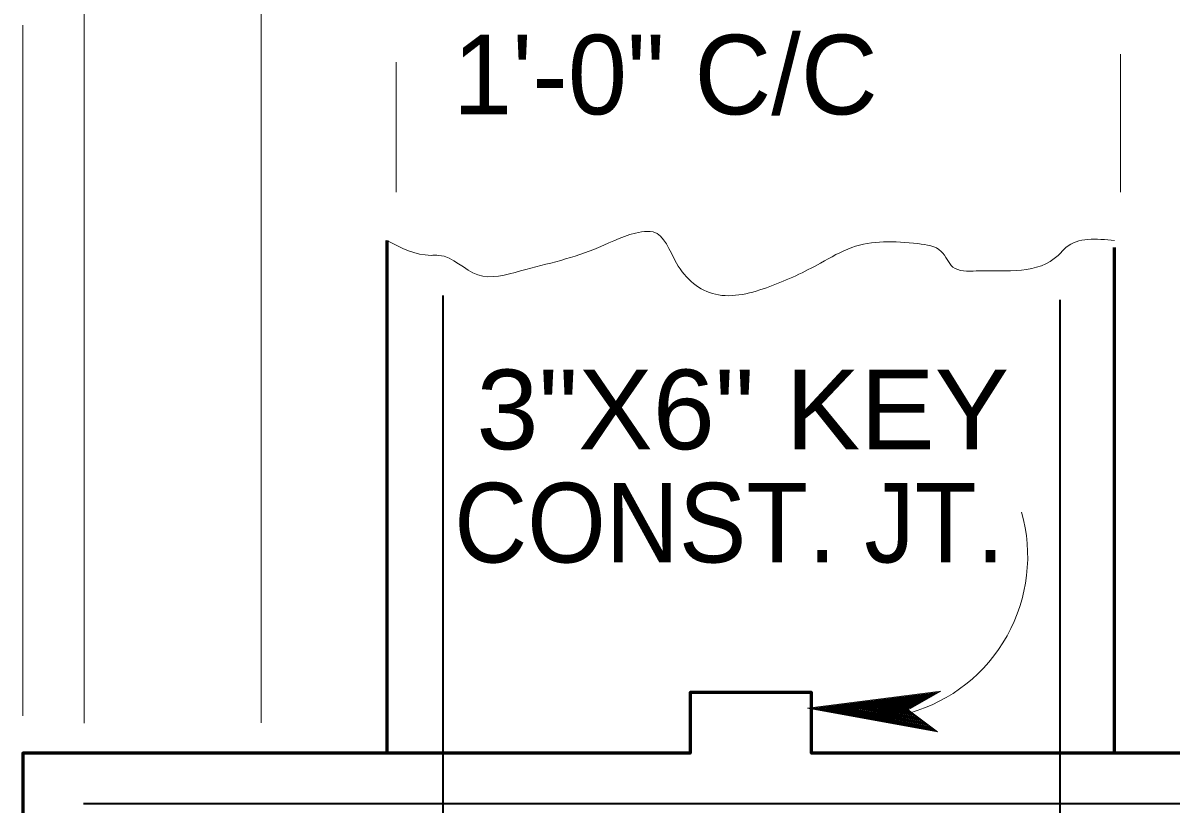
# Model space of a CAD drawing. Extents: x 144 to 252, y 360 to 425.
# Drawn here: x 190.824 to 195.557, y 413.625 to 416.844 of the extents above; entities that cross this region are included whole.
import ezdxf
from ezdxf.enums import TextEntityAlignment as Align

# ---------------------------------------------------------------- set-up
doc = ezdxf.new("R2010")
doc.units = 0
doc.header["$LTSCALE"] = 0.13
for name, color, linetype, lineweight in [('1', 7, 'Continuous', 40), ('14', 7, 'Continuous', 13), ('16', 7, 'Continuous', 13), ('3', 7, 'Continuous', 13), ('4', 7, 'Continuous', 35)]:
    doc.layers.add(name, color=color, linetype=linetype, lineweight=lineweight)

msp = doc.modelspace()

# ---------------------------------------------------------------- linework, layer by layer
at = {"layer": '1', "lineweight": 60}
for p, q in [((192.324, 415.9471), (192.324, 413.8347)), ((195.324, 413.8347), (195.324, 415.9182))]:
    msp.add_line(p, q, dxfattribs=at)
msp.add_lwpolyline([(190.824, 411.8347), (196.824, 411.8347), (196.824, 413.8347), (194.074, 413.8347), (194.074, 414.0847), (193.574, 414.0847), (193.574, 413.8347), (190.824, 413.8347)], close=True, dxfattribs=at)
at = {"layer": '1', "lineweight": 13}
msp.add_spline([(192.324, 415.9471), (192.5062, 415.8861), (192.5383, 415.8861), (192.6989, 415.8058), (192.8755, 415.8218), (193.1967, 415.9182), (193.3732, 415.9824), (193.4214, 415.9824), (193.5178, 415.854), (193.6783, 415.7255), (193.9031, 415.7577), (194.1118, 415.854), (194.2403, 415.9182), (194.5132, 415.9342), (194.6096, 415.9022), (194.6577, 415.8379), (194.7541, 415.8218), (195.0913, 415.8861), (195.1234, 415.9182), (195.324, 415.9471)], degree=3, dxfattribs=at)
at = {"layer": '14', "lineweight": 35}
for points in [[(192.5547, 415.7202), (192.5547, 412.2202), (191.5547, 412.2202)], [(195.0983, 415.7031), (195.0983, 412.2031), (196.0983, 412.2031)]]:
    msp.add_lwpolyline(points, dxfattribs=at)
at = {"layer": '14'}
msp.add_arc((194.2952, 414.6451), 0.6707, 285.8346, 15.8378, dxfattribs=at)
at = {"layer": '3'}
for p, q in [((191.0765, 413.9588), (191.0765, 417.2929)), ((191.8061, 413.9589), (191.8061, 417.2929)), ((190.824, 413.9885), (190.824, 416.8341)), ((190.824, 416.7245), (190.824, 416.7656)), ((192.3625, 416.1465), (192.3625, 416.6827)), ((195.3489, 416.1465), (195.3489, 416.7148)), ((190.824, 414.2097), (190.824, 416.1353)), ((190.824, 414.2097), (190.824, 415.5598)), ((194.6072, 414.0897), (194.0575, 414.0195)), ((194.6012, 414.0863), (194.0718, 414.0187)), ((194.5976, 414.0843), (194.0827, 414.0184)), ((194.5931, 414.0817), (194.0971, 414.0183)), ((194.5888, 414.0793), (194.1098, 414.0181)), ((194.5888, 414.0793), (194.1098, 414.0181)), ((194.5853, 414.0772), (194.1212, 414.0179)), ((194.5806, 414.0746), (194.1357, 414.0178)), ((194.4726, 414.0137), (194.6072, 414.0897)), ((194.5764, 414.0722), (194.1483, 414.0176)), ((194.5721, 414.0697), (194.1621, 414.0174)), ((194.5676, 414.0673), (194.1759, 414.0172)), ((194.5632, 414.0648), (194.1892, 414.017)), ((194.5588, 414.0623), (194.2031, 414.0168)), ((194.5547, 414.0601), (194.2157, 414.0166)), ((194.5509, 414.0578), (194.2272, 414.0165)), ((194.5459, 414.0551), (194.2428, 414.0163)), ((194.5414, 414.0525), (194.2566, 414.0161)), ((194.5342, 414.0484), (194.2746, 414.0154)), ((194.5374, 414.0503), (194.2762, 414.0169)), ((194.5298, 414.0459), (194.2885, 414.0152)), ((194.5255, 414.0435), (194.3017, 414.015)), ((194.5241, 414.0426), (194.3107, 414.0153)), ((194.52, 414.0405), (194.3227, 414.0152)), ((194.5156, 414.0379), (194.3366, 414.015)), ((194.5106, 414.0351), (194.3522, 414.0147)), ((194.5064, 414.0327), (194.3648, 414.0147)), ((194.5023, 414.0302), (194.3782, 414.0144)), ((194.4982, 414.0281), (194.39, 414.0143)), ((194.4936, 414.0254), (194.4046, 414.0141)), ((194.0575, 414.0195), (194.5938, 413.9229)), ((194.4727, 414.0137), (194.0575, 414.0195)), ((194.0718, 414.0187), (194.5906, 413.9253)), ((194.0827, 414.0184), (194.5874, 413.9277)), ((194.0971, 414.0183), (194.5832, 413.9307)), ((194.1098, 414.0181), (194.5795, 413.9335)), ((194.1212, 414.0179), (194.5762, 413.936)), ((194.1357, 414.0178), (194.572, 413.9392)), ((194.1483, 414.0176), (194.5683, 413.942)), ((194.1621, 414.0174), (194.5642, 413.945)), ((194.1759, 414.0172), (194.5602, 413.9481)), ((194.1892, 414.017), (194.5563, 413.951)), ((194.2031, 414.0168), (194.5522, 413.954)), ((194.2157, 414.0166), (194.5486, 413.9567)), ((194.2272, 414.0165), (194.5452, 413.9592)), ((194.2428, 414.0163), (194.5406, 413.9627)), ((194.2566, 414.0161), (194.5366, 413.9658)), ((194.2746, 414.0154), (194.5324, 413.9688)), ((194.2885, 414.0152), (194.5283, 413.9719)), ((194.3017, 414.015), (194.5245, 413.9748)), ((194.3107, 414.0153), (194.5207, 413.9776)), ((194.3227, 414.0152), (194.5172, 413.9803)), ((194.3366, 414.015), (194.5132, 413.9832)), ((194.3522, 414.0147), (194.5085, 413.9867)), ((194.3648, 414.0147), (194.5049, 413.9894)), ((194.3782, 414.0144), (194.501, 413.9923)), ((194.39, 414.0143), (194.4974, 413.995)), ((194.4046, 414.0141), (194.4933, 413.9981)), ((194.4892, 414.0229), (194.4184, 414.0138)), ((194.4184, 414.0138), (194.4892, 414.0011)), ((194.485, 414.0207), (194.4311, 414.0137)), ((194.4311, 414.0137), (194.4855, 414.0039)), ((194.4443, 414.0135), (194.4817, 414.0068)), ((194.4797, 414.0177), (194.4546, 414.0145)), ((194.477, 414.0162), (194.4557, 414.0134)), ((194.4557, 414.0134), (194.4783, 414.0093)), ((194.4659, 414.0132), (194.4752, 414.0116)), ((194.5938, 413.9229), (194.4726, 414.0137))]:
    msp.add_line(p, q, dxfattribs=at)
at = {"layer": '4'}
msp.add_line((196.574, 413.6264), (191.074, 413.6264), dxfattribs=at)

# ---------------------------------------------------------------- texts
at = {"layer": '14'}
for s, width, p in [('3"X6" KEY', 1.05, (192.6931, 415.087)), ('CONST. JT.', 0.95, (192.6017, 414.6204))]:
    msp.add_text(s, height=0.3281, dxfattribs=dict(at, width=width)).set_placement(p)
at = {"layer": '16'}
msp.add_text('1\'-0" C/C', height=0.3281, dxfattribs=at).set_placement((193.472, 416.467), align=Align.CENTER)

doc.saveas('drawing.dxf')
